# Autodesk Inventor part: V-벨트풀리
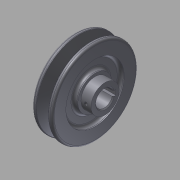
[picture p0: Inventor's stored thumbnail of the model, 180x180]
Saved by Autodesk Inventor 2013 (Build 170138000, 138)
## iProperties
Company: 한국ATC센터
Created: 2014-07
Part Number: V-벨트풀리
Document SubType Name: Modeling
Designer: KYOUNG IL JANG
Density: 7.87 g/cm^3
Material: 강철, 탄소
Mass: 593.765 g
Surface Area: 234.122 cm^2
Volume: 75.4466 cm^3
Author: KYOUNG IL JANG
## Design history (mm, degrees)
sketch "스케치1"
  geometry: L1 (-15, 0)-(15, 0); L2 (-15, 0)-(-15, 17); L3 (-15, 17)-(-11, 17); L4 (-11, 17)-(-11, 29); L5 (-11, 29)-(-15, 29); L6 (-15, 29)-(-15, 42.5); L7 (-15, 42.5)-(-10.976, 42.5); L8 (-10.976, 42.5)-(-7.154, 30); L9 (-7.154, 30)-(-2.846, 30); L10 (-2.846, 30)-(0.976, 42.5); L11 (0.976, 42.5)-(5, 42.5); L12 (5, 42.5)-(5, 29); L13 (5, 29)-(1, 29); L14 (1, 29)-(1, 17); L15 (1, 17)-(5, 17); L16 (5, 17)-(5, 14); L17 (5, 14)-(15, 14); L18 (15, 14)-(15, 0); L19 (-9.6, 38)-(-0.4, 38); 2 further points
  constraints: 38 end point, 11 parallel, 7 collinear, 3 equal length, 3 perpendicular, 2 point on line, 1 coincident, 1 horizontal, 1 midpoint
  dimensions: "d0" = 30 distance of L1.start L1.end; "d1" = 4.5 distance between parallel lines of L7 L19; "d2" = 8 distance between parallel lines of L9 L19; "d3" = 9.2 distance of L19.start L19.end; "d4" = 34 deg angle of L10 L8; "d5" = 20 distance between parallel lines of L12 L6; "d6" = 76 diameter of L19 L1; "d7" = 4 distance of L2.end L3.end; "d8" = 34 diameter of L3 L1; "d9" = 58 diameter of L5 L1; "d10" = 28 diameter of L17 L1
revolve "회전1" sketch "스케치1" stored, may be unused: angle "d11" = 90 deg
sketch "스케치2"
  geometry: L1 (-2.5, 8.124)-(-2.5, 10.8); L2 (-2.5, 10.8)-(2.5, 10.8); L3 (2.5, 10.8)-(2.5, 8.124); A1 r 8.5 centre (0, 0) between (-2.5, 8.124) and (2.5, 8.124); 1 further point
  constraints: 6 end point, 2 parallel, 2 point on circle, 1 centre point, 1 coincident, 1 horizontal, 1 vertical
  dimensions: "d12" = 17 diameter of A1; "d13" = 5 distance of L1.end L2.end; "d14" = 19.3 dimension on A1 L2 (computed from d12)
extrude "돌출1" cut sketch "스케치2" stored distance "d15" = 10; taper "d16" = 0 deg
chamfer "모따기1" distance "d17" = 1; stored, may be unused: second distance "d18" = 2, angle "d19" = 45 deg
node "작업 평면1"
sketch "스케치3"
  geometry: L1 (5, -14)-(5, 14) reference; 3 further points
  constraints: 1 horizontal alignment, 1 midpoint
  dimensions: "d20" = 5 distance from line of L1 point (0, 0)
hole "구멍1" sketch "스케치3" at (0, 0) diameter "d21" = 3.242; stored, may be unused: countersink angle "d25" = 90 deg, drill point angle "d27" = 118 deg; dims "d22" = 6, "d23" = 4, "d24" = 2, "d26" = 8
fillet "모깎기1" dims "d28" = 3, "d29" = 2, "d30" = 0.5, "d31" = 1
node "솔리드1"
